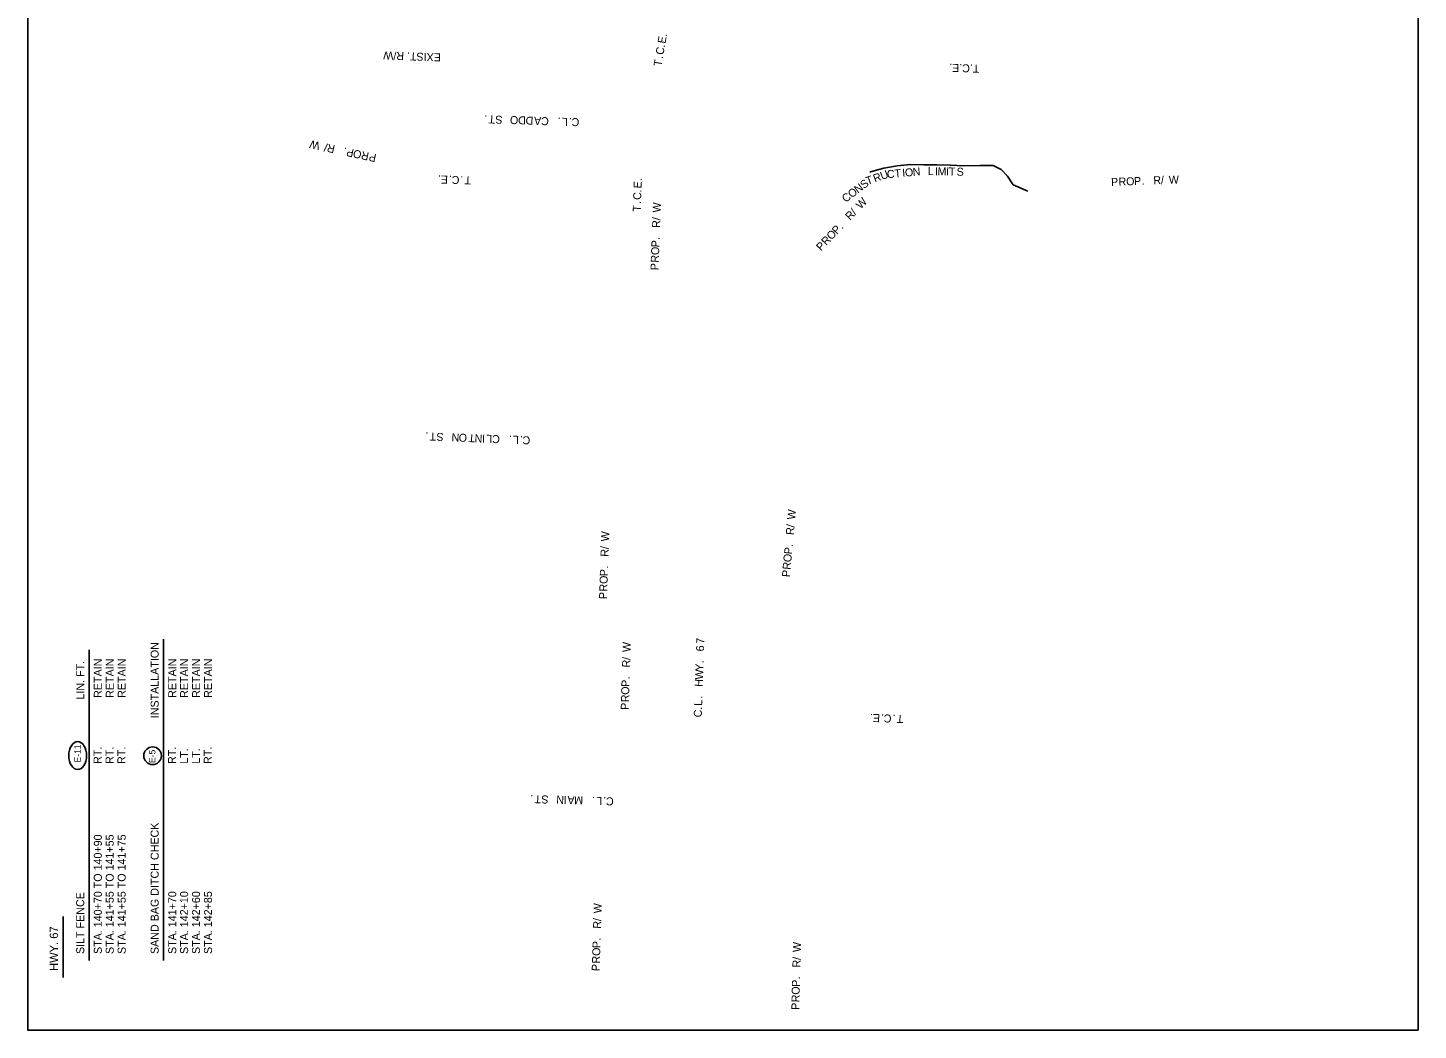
# Model space of a CAD drawing. Extents: x 991974 to 993016, y 1842702 to 1844298.
# Drawn here: x 991974 to 993016, y 1842702 to 1843454 of the extents above; entities that cross this region are included whole.
import ezdxf

# ---------------------------------------------------------------- set-up
doc = ezdxf.new("R2010")
doc.units = 0
for name, color, linetype in [('1', 7, 'Continuous'), ('44', 7, 'Continuous'), ('Default', 7, 'Continuous'), ('R_Draft', 7, 'Continuous'), ('R_Proposed Const Limits', 7, 'Continuous')]:
    doc.layers.add(name, color=color, linetype=linetype)

msp = doc.modelspace()

# ---------------------------------------------------------------- linework, layer by layer
at = {"layer": '1'}
msp.add_circle((992067.6, 1842908.3), 6.61, dxfattribs=at)
msp.add_ellipse((992011.4, 1842908.4), major_axis=(0, 10.5), ratio=0.638788, dxfattribs=at)
at = {"layer": '44'}
for p, q in [((992075.8, 1842754.8), (992075.8, 1842995.8)), ((992020.1, 1842754.8), (992020.1, 1842987.6)), ((992000.5, 1842742.1), (992000.5, 1842787.7))]:
    msp.add_line(p, q, dxfattribs=at)
at = {"layer": 'Default'}
msp.add_lwpolyline([(993016.3, 1842702.5), (991974, 1842702.5), (991974, 1843999.5), (992023.6, 1843999.5), (992023.6, 1844170.3), (992171.1, 1844170.3), (992171.1, 1844297.8), (993016.3, 1844297.8)], close=True, dxfattribs=at)
msp.add_lwpolyline([(993016.3, 1842702.5), (991974, 1842702.5), (991974, 1843999.5), (992023.6, 1843999.5), (992023.6, 1844170.3), (992171.1, 1844170.3), (992171.1, 1844297.8), (993016.3, 1844297.8)], close=True, dxfattribs=at)
at = {"layer": 'R_Proposed Const Limits'}
msp.add_lwpolyline([(992605.2, 1843346), (992605.7, 1843346.2), (992615.7, 1843348.9), (992625.8, 1843350.7), (992635.8, 1843351.7), (992645.8, 1843351.4), (992655.8, 1843351.3), (992665.8, 1843351.1), (992675.8, 1843350.7), (992687.8, 1843350.8), (992697.6, 1843350.8), (992703.8, 1843347.9), (992708.4, 1843342.9), (992712.8, 1843336.3), (992723.8, 1843331.5)], dxfattribs=at)

# ---------------------------------------------------------------- texts
at = {"layer": '1'}
for s, p in [('E-11', (992013.7, 1842903.2)), ('E-5 ', (992069.7, 1842902.8))]:
    msp.add_text(s, height=4.8, rotation=90, dxfattribs=at).set_placement(p)
at = {"layer": '44'}
for s, height, p in [('INSTALLATION', 6, (992072.1, 1842936.4)), ('LIN. FT.', 6, (992016.3, 1842950.4)), ('RETAIN', 6, (992029.5, 1842951.7)), ('RETAIN', 6, (992038.5, 1842951.7)), ('RETAIN', 6, (992047.4, 1842951.7)), ('RT.', 6, (992029.3, 1842902.1)), ('RT.', 6, (992038.3, 1842902.1)), ('RT.', 6, (992047.2, 1842902.1)), ('SAND BAG DITCH CHECK', 6, (992072.1, 1842759.6)), ('STA. 140+70 TO 140+90', 6, (992029.5, 1842759.6)), ('STA. 141+55 TO 141+55', 6, (992038.4, 1842759.6)), ('STA. 141+55 TO 141+75', 6, (992047.4, 1842759.6)), ('SILT FENCE      ', 6, (992016.3, 1842759.6)), ('HWY. 67', 6.25, (991996.7, 1842746.9))]:
    msp.add_text(s, height=height, rotation=90, dxfattribs=at).set_placement(p)
at = {"layer": 'R_Draft'}
for s, rotation, p in [('E', 80.3144, (992452, 1843442)), ('.', 80.3144, (992452.9, 1843447.3)), ('C', 80.3144, (992450.5, 1843433.5)), ('.', 80.3144, (992451.5, 1843439.1)), ('EXIST. R/W', 178.0562, (992283.8, 1843434.9)), ('T', 80.3144, (992449, 1843424.9)), ('.', 80.3144, (992450, 1843430.7)), ('T.C.E.', 178.0361, (992687.5, 1843426.4)), ('.', 178.1194, (992318.4, 1843388.5)), ('T', 178.1194, (992324.3, 1843388.3)), ('S', 178.1194, (992330, 1843388.1)), ('O', 178.1194, (992341.8, 1843387.8)), ('D', 178.1194, (992347.5, 1843387.6)), ('D', 178.1194, (992353.1, 1843387.4)), ('A', 178.1194, (992359, 1843387.2)), ('C', 178.1194, (992364.7, 1843387)), ('.', 178.1194, (992373.6, 1843386.7)), ('L', 178.1194, (992379, 1843386.5)), ('.', 178.1194, (992381.9, 1843386.4)), ('C', 178.1194, (992387.6, 1843386.3)), ('W', 167.7876, (992193.4, 1843368.3)), ('/', 167.7876, (992199.1, 1843367.1)), ('R', 167.7876, (992204.7, 1843365.9)), ('.', 167.7876, (992213.4, 1843364)), ('P', 167.7876, (992218.9, 1843362.8)), ('O', 167.7876, (992224.7, 1843361.6)), ('R', 167.7876, (992230.2, 1843360.4)), ('P', 167.7876, (992235.7, 1843359.2)), ('.', 178.0318, (992283.7, 1843343.4)), ('E', 178.0318, (992289.1, 1843343.2)), ('.', 178.0318, (992292, 1843343.1)), ('C', 178.0318, (992297.7, 1843342.9)), ('T', 19.6124, (992603.5, 1843336.2)), ('R', 19.6124, (992609, 1843338.1)), ('U', 19.6124, (992614.3, 1843340)), ('C', 4.7945, (992618.3, 1843341.3)), ('T', 4.7945, (992624, 1843341.8)), ('I', 4.7945, (992629.8, 1843342.3)), ('O', 4.7945, (992631.8, 1843342.5)), ('N', 4.7945, (992637.6, 1843343)), ('L', 358.9403, (992648.6, 1843343.7)), ('I', 358.9403, (992654, 1843343.6)), ('M', 358.9403, (992656, 1843343.5)), ('I', 358.9403, (992662.4, 1843343.4)), ('T', 358.9403, (992664.4, 1843343.4)), ('S', 359.7068, (992670.3, 1843343.2)), ('/', 2.1217, (992823.6, 1843336.9)), ('W', 2.1217, (992829.5, 1843337.1)), ('.', 178.0318, (992300.6, 1843342.8)), ('T', 178.0318, (992306.5, 1843342.6)), ('E', 88.0361, (992434.1, 1843333.6)), ('.', 88.0361, (992434.3, 1843339)), ('O', 36.989, (992591.6, 1843326.2)), ('N', 36.989, (992596.3, 1843329.7)), ('S', 36.989, (992600.8, 1843333.1)), ('P', 2.1217, (992786.2, 1843335.5)), ('R', 2.1217, (992791.8, 1843335.7)), ('O', 2.1217, (992797.5, 1843335.9)), ('P', 2.1217, (992803.4, 1843336.1)), ('.', 2.1217, (992809, 1843336.4)), ('R', 2.1217, (992817.9, 1843336.7)), ('C', 88.0361, (992433.8, 1843325)), ('.', 88.0361, (992433.7, 1843322.1)), ('.', 88.0361, (992434, 1843330.6)), ('W', 87.8155, (992448.4, 1843315.5)), ('C', 36.989, (992587.1, 1843322.8)), ('W', 46.5037, (992598.5, 1843317.8)), ('T', 88.0361, (992433.5, 1843316.2)), ('/', 87.8155, (992448.2, 1843309.7)), ('R', 46.5037, (992590.5, 1843309.4)), ('/', 46.5037, (992594.4, 1843313.5)), ('R', 87.8155, (992448, 1843304)), ('O', 46.5037, (992576.5, 1843294.6)), ('P', 46.5037, (992580.5, 1843298.8)), ('.', 46.5037, (992584.4, 1843302.9)), ('P', 87.8155, (992447.4, 1843289.4)), ('.', 87.8155, (992447.7, 1843295.1)), ('P', 46.5037, (992568.7, 1843286.4)), ('R', 46.5037, (992572.6, 1843290.5)), ('R', 87.8155, (992447, 1843277.9)), ('O', 87.8155, (992447.2, 1843283.6)), ('P', 87.8155, (992446.8, 1843272.2)), ('.', 177.7861, (992274.4, 1843150.7)), ('T', 177.7861, (992280.2, 1843150.5)), ('S', 177.7861, (992285.9, 1843150.2)), ('N', 177.7861, (992297.6, 1843149.8)), ('O', 177.7861, (992303.4, 1843149.6)), ('T', 177.7861, (992309.3, 1843149.3)), ('N', 177.7861, (992314.9, 1843149.1)), ('I', 177.7861, (992316.9, 1843149)), ('L', 177.7861, (992322.3, 1843148.8)), ('C', 177.7861, (992328, 1843148.6)), ('.', 177.7861, (992336.9, 1843148.3)), ('L', 177.7861, (992342.3, 1843148.1)), ('.', 177.7861, (992345.2, 1843148)), ('C', 177.7861, (992350.8, 1843147.7)), ('W', 84.7809, (992549.2, 1843085.1)), ('W', 88.0361, (992409.7, 1843068.9)), ('R', 84.7809, (992548.2, 1843073.6)), ('/', 84.7809, (992548.7, 1843079.3)), ('/', 88.0361, (992409.5, 1843063.1)), ('R', 88.0361, (992409.3, 1843057.4)), ('P', 84.7809, (992546.9, 1843059.1)), ('.', 84.7809, (992547.4, 1843064.7)), ('R', 84.7809, (992545.8, 1843047.6)), ('O', 84.7809, (992546.3, 1843053.2)), ('O', 88.0361, (992408.6, 1843037)), ('P', 88.0361, (992408.8, 1843042.8)), ('.', 88.0361, (992409, 1843048.5)), ('P', 84.7809, (992545.3, 1843042)), ('P', 88.0361, (992408.2, 1843025.6)), ('R', 88.0361, (992408.4, 1843031.3)), ('W', 88.2135, (992425.8, 1842985.9)), ('6', 88.0361, (992480.9, 1842986.4)), ('7', 88.0361, (992481.1, 1842992.1)), ('RETAIN', 90, (992085.3, 1842951.7)), ('RETAIN', 90, (992094.2, 1842951.7)), ('RETAIN', 90, (992103.2, 1842951.7)), ('RETAIN', 90, (992112.1, 1842951.7)), ('/', 88.2135, (992425.7, 1842980)), ('R', 88.2135, (992425.5, 1842974.4)), ('.', 88.0361, (992480.6, 1842977.5)), ('W', 88.0361, (992480.2, 1842965.3)), ('Y', 88.0361, (992480.4, 1842971.8)), ('O', 88.2135, (992424.8, 1842953.9)), ('P', 88.2135, (992425, 1842959.8)), ('.', 88.2135, (992425.2, 1842965.5)), ('H', 88.0361, (992480, 1842959.9)), ('P', 88.2135, (992424.5, 1842942.6)), ('R', 88.2135, (992424.7, 1842948.3)), ('L', 88.0361, (992479.5, 1842945.6)), ('.', 88.0361, (992479.7, 1842951)), ('C', 88.0361, (992479.2, 1842937)), ('.', 88.0361, (992479.4, 1842942.7)), ('.', 178.0361, (992607.7, 1842939.6)), ('E', 178.0361, (992613, 1842939.4)), ('.', 178.0361, (992616, 1842939.3)), ('C', 178.0361, (992621.6, 1842939.1)), ('.', 178.0361, (992624.6, 1842939)), ('T', 178.0361, (992630.4, 1842938.8)), ('RT.', 90, (992085.1, 1842902.1)), ('LT.', 90, (992094.1, 1842902.3)), ('LT.', 90, (992103, 1842902.3)), ('RT.', 90, (992111.9, 1842902.1)), ('.', 178.3694, (992352.9, 1842878.8)), ('T', 178.3694, (992358.8, 1842878.6)), ('S', 178.3694, (992364.5, 1842878.4)), ('N', 178.3694, (992376.1, 1842878.1)), ('I', 178.3694, (992378.1, 1842878)), ('A', 178.3694, (992384, 1842877.9)), ('M', 178.3694, (992390.4, 1842877.7)), ('.', 178.3694, (992399.3, 1842877.4)), ('L', 178.3694, (992404.7, 1842877.3)), ('.', 178.3694, (992407.6, 1842877.2)), ('C', 178.3694, (992413.3, 1842877)), ('STA. 141+70', 90, (992085.3, 1842759.6)), ('STA. 142+10', 90, (992094.2, 1842759.6)), ('STA. 142+60', 90, (992103.1, 1842759.6)), ('STA. 142+85', 90, (992112.1, 1842759.6)), ('W', 88.2135, (992404.1, 1842790)), ('/', 88.2135, (992403.9, 1842784.2)), ('R', 88.2135, (992403.7, 1842778.5)), ('.', 88.2135, (992403.4, 1842769.6)), ('O', 88.2135, (992403.1, 1842758.1)), ('P', 88.2135, (992403.3, 1842763.9)), ('W', 88.2437, (992553.5, 1842760.9)), ('P', 88.2135, (992402.7, 1842746.7)), ('R', 88.2135, (992402.9, 1842752.4)), ('/', 88.3031, (992553.3, 1842755.1)), ('R', 88.3605, (992553.2, 1842749.4)), ('P', 88.5084, (992552.8, 1842734.9)), ('.', 88.4509, (992552.9, 1842740.5)), ('R', 88.6251, (992552.5, 1842723.3)), ('O', 88.5677, (992552.6, 1842729)), ('P', 88.6826, (992552.4, 1842717.7))]:
    msp.add_text(s, height=6, rotation=rotation, dxfattribs=at).set_placement(p)

doc.saveas('drawing.dxf')
